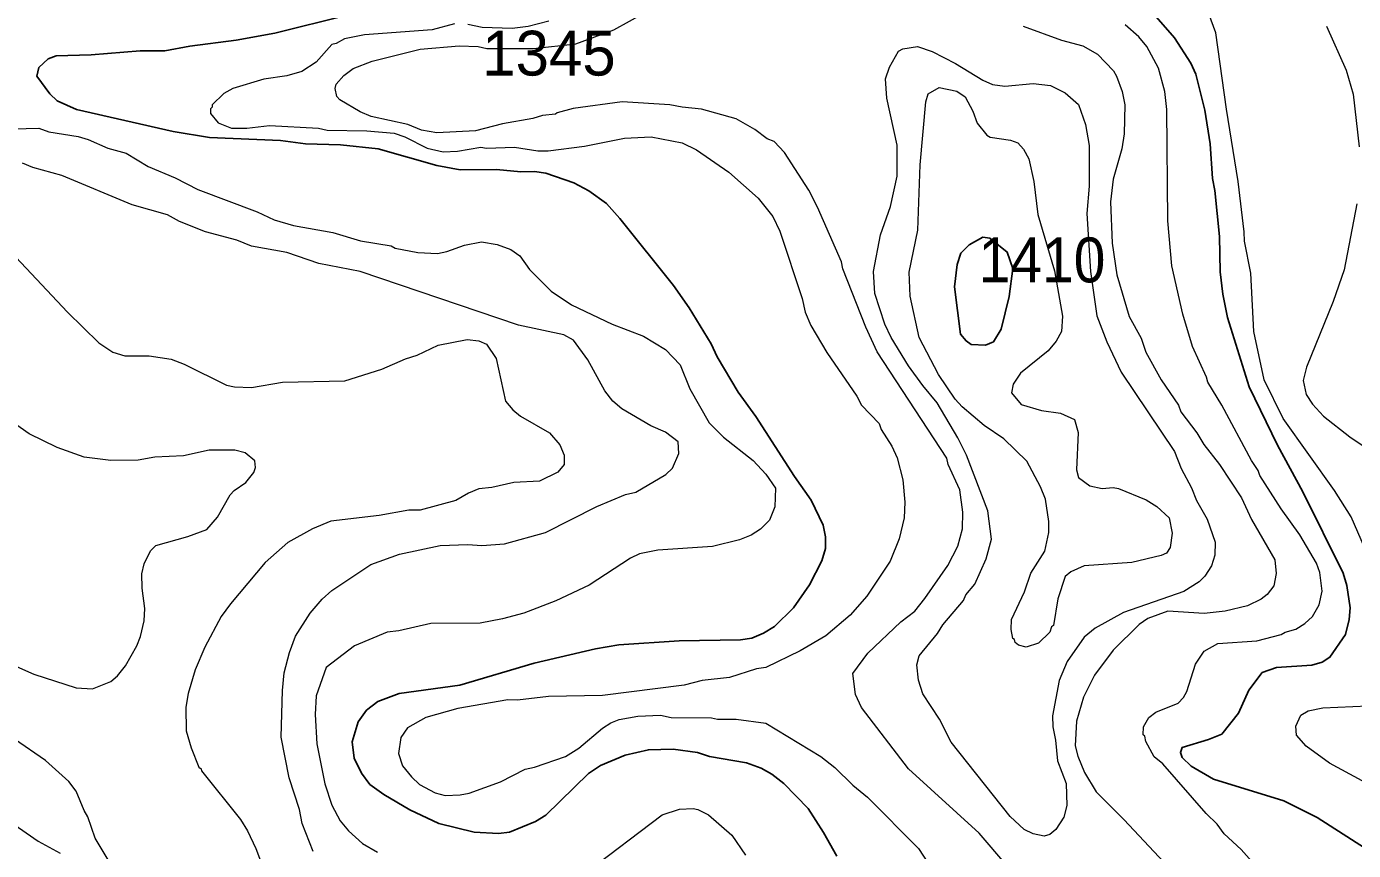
# Model space of a CAD drawing. Extents: x 598.3 to 623.2, y 6902.2 to 6930.1.
# Drawn here: x 600.767 to 603.134, y 6914.004 to 6915.474 of the extents above; entities that cross this region are included whole.
import ezdxf

# ---------------------------------------------------------------- set-up
doc = ezdxf.new("R2010")
doc.units = 0
doc.header["$LTSCALE"] = 0.032
doc.layers.add('1', color=7, linetype='Continuous', lineweight=25)
doc.layers.add('2', color=7, linetype='Continuous', lineweight=13)
doc.layers.add('21', color=7, linetype='Continuous')

msp = doc.modelspace()

# ---------------------------------------------------------------- linework, layer by layer
at = {"layer": '1'}
for points in [[(602.7571, 6915.5205), (602.8149, 6915.4545), (602.8438, 6915.4089), (602.8527, 6915.3895), (602.8692, 6915.3253), (602.8787, 6915.2648), (602.8827, 6915.203), (602.8869, 6915.1816), (602.8949, 6915.0997), (602.8965, 6915.0365), (602.9013, 6914.9965), (602.9095, 6914.955), (602.9478, 6914.8315), (602.9985, 6914.727), (603.044, 6914.6442), (603.1158, 6914.499), (603.1225, 6914.477), (603.128, 6914.4369), (603.1264, 6914.4162), (603.1199, 6914.3894), (603.0922, 6914.3488), (603.0781, 6914.3402)], [(602.1883, 6914.5842), (602.1668, 6914.629), (602.1368, 6914.6711), (602.0681, 6914.7782), (602.0364, 6914.8216), (601.9992, 6914.885), (601.9883, 6914.9083), (601.949, 6914.9722), (601.9213, 6915.0123), (601.8254, 6915.132), (601.8013, 6915.1585), (601.7702, 6915.1813), (601.7433, 6915.1956), (601.6933, 6915.2128), (601.6729, 6915.2159), (601.6484, 6915.2152), (601.6055, 6915.2193), (601.5406, 6915.2188), (601.499, 6915.2266), (601.3941, 6915.2564), (601.327, 6915.263), (601.2646, 6915.2653), (601.2196, 6915.271), (601.0929, 6915.2765), (601.0282, 6915.2872), (600.8559, 6915.3263), (600.8213, 6915.3419), (600.8085, 6915.3541), (600.7854, 6915.3858), (600.7887, 6915.4013), (600.8054, 6915.4166), (600.8194, 6915.4223), (600.8822, 6915.424), (600.9696, 6915.4312), (601.0134, 6915.4312), (601.0582, 6915.4395), (601.1406, 6915.45), (601.2095, 6915.4628), (601.3388, 6915.4944)], [(602.2125, 6913.9936), (602.1889, 6914.036), (602.1612, 6914.0788), (602.1181, 6914.1237), (602.0965, 6914.1403), (602.0776, 6914.1505), (602.0515, 6914.1606), (601.9853, 6914.1717), (601.964, 6914.179), (601.9206, 6914.1846), (601.8763, 6914.1838), (601.8345, 6914.1741), (601.7908, 6914.1555), (601.7696, 6914.1414), (601.6934, 6914.0672), (601.6749, 6914.0555), (601.6286, 6914.0365), (601.6085, 6914.0342), (601.5654, 6914.0366), (601.5025, 6914.0522), (601.4508, 6914.0762), (601.404, 6914.1039), (601.3793, 6914.1218), (601.3645, 6914.1417), (601.3512, 6914.1688), (601.348, 6914.1979), (601.3586, 6914.2332), (601.373, 6914.2541), (601.3933, 6914.2696), (601.4316, 6914.2843), (601.5401, 6914.2989), (601.6724, 6914.338), (601.7817, 6914.3637), (601.8234, 6914.3709), (601.9309, 6914.3781), (602.0404, 6914.3798), (602.0608, 6914.383), (602.0815, 6914.3916), (602.1011, 6914.4035), (602.135, 6914.437), (602.1639, 6914.4779), (602.1855, 6914.5207), (602.1922, 6914.5426), (602.1922, 6914.5638), (602.1883, 6914.5842)], [(603.0781, 6914.3402), (603.06, 6914.3345), (602.9969, 6914.3303), (602.9713, 6914.3215), (602.9477, 6914.2902), (602.9293, 6914.2488), (602.8991, 6914.2116), (602.8758, 6914.2017), (602.8286, 6914.1878), (602.8255, 6914.1788), (602.8288, 6914.1698), (602.8443, 6914.1543), (602.8843, 6914.1309), (603.0102, 6914.0923), (603.0696, 6914.0626), (603.1537, 6914.0084)]]:
    msp.add_lwpolyline(points, dxfattribs=at)
msp.add_lwpolyline([(602.5055, 6914.934), (602.5201, 6914.9924), (602.5262, 6915.0424), (602.5162, 6915.0718), (602.4856, 6915.0967), (602.473, 6915.0985), (602.4483, 6915.085), (602.4336, 6915.0701), (602.4271, 6915.0495), (602.4222, 6915.0096), (602.4332, 6914.9252), (602.443, 6914.9134), (602.4519, 6914.9069), (602.4779, 6914.9058), (602.4919, 6914.9119)], close=True, dxfattribs=at)
at = {"layer": '2'}
for points in [[(601.7136, 6915.3205), (601.7105, 6915.3178), (601.6871, 6915.3155), (601.6701, 6915.3104), (601.6162, 6915.301), (601.5676, 6915.2881), (601.4987, 6915.2846), (601.4716, 6915.2897), (601.4473, 6915.2994), (601.3818, 6915.3138), (601.3617, 6915.322), (601.3255, 6915.3436), (601.3201, 6915.3495), (601.3173, 6915.364), (601.319, 6915.3714), (601.3327, 6915.3869), (601.3494, 6915.3992), (601.3831, 6915.4127), (601.4689, 6915.4338), (601.5386, 6915.4402), (601.5725, 6915.4385), (601.5879, 6915.4354), (601.6715, 6915.4349), (601.7467, 6915.4435), (601.8145, 6915.4683), (601.8984, 6915.515)], [(603.1597, 6914.5309), (603.1303, 6914.5994), (603.1005, 6914.6461), (603.0089, 6914.7746), (602.9747, 6914.8439), (602.9563, 6914.9303), (602.9508, 6915.0344), (602.9395, 6915.0911), (602.9394, 6915.1078), (602.9282, 6915.1979), (602.9077, 6915.3269), (602.8885, 6915.4634), (602.8677, 6915.5195)], [(601.6988, 6915.4841), (601.6618, 6915.4742), (601.6329, 6915.471), (601.5798, 6915.4726), (601.5539, 6915.4783)], [(601.5301, 6915.479), (601.4902, 6915.4686), (601.3696, 6915.4598), (601.3342, 6915.4523), (601.3192, 6915.4441), (601.3112, 6915.4423), (601.2836, 6915.4107), (601.2578, 6915.3939), (601.2313, 6915.3865), (601.1904, 6915.3803), (601.1346, 6915.3639), (601.1185, 6915.3548), (601.098, 6915.3349), (601.0978, 6915.3304), (601.0947, 6915.3274), (601.0949, 6915.3194), (601.1084, 6915.3028), (601.1324, 6915.2933), (601.16, 6915.2929), (601.2004, 6915.2977), (601.2876, 6915.2928), (601.3029, 6915.2897), (601.3737, 6915.288), (601.4228, 6915.284), (601.4417, 6915.2775), (601.4815, 6915.2572), (601.5102, 6915.2508), (601.5357, 6915.2522), (601.5771, 6915.2588), (601.5872, 6915.2572)], [(602.5447, 6915.4749), (602.613, 6915.45), (602.6512, 6915.4397), (602.6776, 6915.4252), (602.7058, 6915.3952), (602.7116, 6915.3857), (602.7217, 6915.3582), (602.7265, 6915.3344), (602.725, 6915.2826), (602.7207, 6915.2559), (602.7055, 6915.202), (602.7007, 6915.1618), (602.7038, 6915.088), (602.712, 6915.0312), (602.7339, 6914.9566), (602.7555, 6914.9183), (602.764, 6914.8933), (602.7912, 6914.8439), (602.8218, 6914.7985), (602.8263, 6914.7866), (602.8546, 6914.7495), (602.8669, 6914.7282), (602.8949, 6914.693), (602.9345, 6914.6331), (602.9522, 6914.5946), (602.9937, 6914.5225), (602.9961, 6914.4982), (602.992, 6914.4764), (602.9801, 6914.461), (602.9694, 6914.4526), (602.9452, 6914.4405), (602.9052, 6914.4308), (602.868, 6914.4268), (602.8027, 6914.4307), (602.767, 6914.4178), (602.7517, 6914.4074), (602.7057, 6914.3613), (602.672, 6914.3169)], [(602.9619, 6914.3782), (603.0053, 6914.3895), (603.0122, 6914.3937), (603.0315, 6914.399), (603.0471, 6914.4088), (603.0609, 6914.4212), (603.073, 6914.4424), (603.0786, 6914.4665), (603.0739, 6914.5002), (603.068, 6914.5168), (603.0384, 6914.5673), (603.0052, 6914.6135), (602.9671, 6914.6734), (602.9642, 6914.6823), (602.9521, 6914.7), (602.8991, 6914.7988), (602.8741, 6914.8398), (602.8721, 6914.8487), (602.8472, 6914.9033), (602.8299, 6914.961), (602.81, 6915.0474), (602.8027, 6915.1276), (602.801, 6915.3266), (602.7978, 6915.3582), (602.7865, 6915.4003), (602.7654, 6915.4385), (602.7512, 6915.456), (602.7271, 6915.4776)], [(603.0861, 6915.4748), (603.1213, 6915.3963), (603.1338, 6915.3534), (603.1443, 6915.2595)], [(602.5156, 6913.9772), (602.4662, 6914.0345), (602.3401, 6914.1494), (602.2562, 6914.2591), (602.2457, 6914.2821), (602.241, 6914.3198), (602.2675, 6914.3563), (602.3268, 6914.4122), (602.3513, 6914.4311), (602.3697, 6914.4537), (602.4103, 6914.5123), (602.4282, 6914.5467), (602.4367, 6914.5779), (602.4375, 6914.6075), (602.4319, 6914.6477), (602.4111, 6914.6925), (602.4084, 6914.7043), (602.2844, 6914.8941), (602.2642, 6914.9378), (602.2234, 6915.0418), (602.2205, 6915.0543), (602.178, 6915.1523), (602.1622, 6915.1822), (602.119, 6915.2494), (602.1009, 6915.2692), (602.0883, 6915.2737), (602.066, 6915.2904), (602.0331, 6915.3097), (601.9708, 6915.3268), (601.9363, 6915.3302), (601.9144, 6915.3349), (601.8292, 6915.3399), (601.7423, 6915.3279), (601.7136, 6915.3205)], [(600.7217, 6915.2913), (600.7886, 6915.2928), (600.8064, 6915.2863), (600.8588, 6915.2781), (600.8768, 6915.273), (600.9117, 6915.2573), (600.9443, 6915.2482), (600.984, 6915.2243), (601.0318, 6915.2045), (601.0724, 6915.1833), (601.1781, 6915.1436), (601.2087, 6915.1297), (601.2428, 6915.1194), (601.313, 6915.1067), (601.3626, 6915.0919), (601.4174, 6915.0832), (601.4242, 6915.079), (601.4648, 6915.0711), (601.4999, 6915.0695), (601.5169, 6915.073), (601.5482, 6915.0841), (601.5782, 6915.0903), (601.6065, 6915.0856), (601.6308, 6915.0766), (601.6469, 6915.0651), (601.664, 6915.0406), (601.7029, 6915.0018), (601.739, 6914.9779), (601.8118, 6914.9431), (601.8672, 6914.922), (601.9069, 6914.8982), (601.933, 6914.8707), (601.95, 6914.8277), (601.9849, 6914.767), (602.0101, 6914.7415), (602.0632, 6914.6999), (602.0858, 6914.6757), (602.1031, 6914.6507), (602.1016, 6914.6169), (602.0922, 6914.5931), (602.076, 6914.5774), (602.0593, 6914.5666), (602.0386, 6914.5582), (601.9905, 6914.5466)], [(601.5872, 6915.2572), (601.6373, 6915.2588), (601.6787, 6915.2525), (601.6975, 6915.2524), (601.7623, 6915.261), (601.8335, 6915.2751), (601.8809, 6915.2774), (601.9363, 6915.267), (601.9621, 6915.2542), (602.0196, 6915.2145), (602.072, 6915.1679), (602.0982, 6915.1352), (602.1106, 6915.1089), (602.1503, 6914.9888), (602.1559, 6914.9648), (602.1663, 6914.9407), (602.1944, 6914.8926), (602.248, 6914.8146), (602.2567, 6914.7987), (602.2877, 6914.7659), (602.2916, 6914.755), (602.3103, 6914.7257), (602.3202, 6914.7049), (602.33, 6914.6653), (602.3339, 6914.6253), (602.3323, 6914.5975), (602.3234, 6914.5603), (602.3075, 6914.5203), (602.2657, 6914.458), (602.2364, 6914.4239), (602.1925, 6914.3872), (602.147, 6914.36), (602.0857, 6914.3304), (602.069, 6914.3279), (602.021, 6914.3126), (601.9724, 6914.307), (601.9403, 6914.2989), (601.7943, 6914.2802), (601.698, 6914.2785), (601.6424, 6914.2721), (601.6256, 6914.2729), (601.5364, 6914.2575), (601.4791, 6914.241), (601.4462, 6914.2229), (601.4346, 6914.2057), (601.4306, 6914.177), (601.4373, 6914.1551), (601.4534, 6914.1351), (601.4678, 6914.1217), (601.496, 6914.1065), (601.5137, 6914.1022), (601.5404, 6914.103), (601.5563, 6914.1062), (601.6125, 6914.1263), (601.6564, 6914.149), (601.6729, 6914.1523), (601.7282, 6914.1717), (601.7523, 6914.1863), (601.7942, 6914.2221), (601.8091, 6914.2319), (601.8243, 6914.2379), (601.8574, 6914.2438), (601.8976, 6914.2453), (601.9168, 6914.2414), (601.9888, 6914.2406), (601.9994, 6914.2381), (602.0326, 6914.238), (602.0857, 6914.2309), (602.1839, 6914.1714), (602.2089, 6914.1519), (602.2408, 6914.1202), (602.2671, 6914.0993), (602.3584, 6914.0072), (602.4235, 6913.9068)], [(601.7251, 6914.9241), (601.6443, 6914.9413), (601.362, 6915.037), (601.2882, 6915.0514), (601.2309, 6915.071), (601.1679, 6915.0825), (601.1419, 6915.0929), (601.0858, 6915.1081), (601.0396, 6915.1265), (601.0183, 6915.1383), (600.9552, 6915.1564), (600.83, 6915.2083), (600.7779, 6915.2231), (600.7598, 6915.2305)], [(603.1402, 6915.158), (603.1173, 6915.0402), (603.0978, 6914.9836), (603.0503, 6914.8662), (603.0447, 6914.8429), (603.0497, 6914.8175), (603.0608, 6914.8004), (603.0809, 6914.779), (603.1279, 6914.7419), (603.173, 6914.712)], [(600.7293, 6915.0826), (600.8397, 6914.9648), (600.896, 6914.9101), (600.9209, 6914.893), (600.9424, 6914.8865), (600.9856, 6914.8865), (601.0248, 6914.8809), (601.048, 6914.8718), (601.1233, 6914.8343), (601.1377, 6914.8313), (601.1681, 6914.8299), (601.2235, 6914.8395), (601.3348, 6914.8419), (601.4004, 6914.8629), (601.4427, 6914.8816), (601.4635, 6914.888), (601.5013, 6914.906), (601.5526, 6914.9156), (601.5736, 6914.9133), (601.5875, 6914.9074), (601.6046, 6914.8819), (601.6213, 6914.8057), (601.6344, 6914.7904), (601.6479, 6914.7792), (601.6999, 6914.749), (601.7182, 6914.7281), (601.726, 6914.7092), (601.726, 6914.6925), (601.7145, 6914.6791), (601.6819, 6914.6631)], [(601.2781, 6914.0022), (601.2585, 6914.0518), (601.2539, 6914.0768), (601.2352, 6914.1338), (601.2209, 6914.2064), (601.2234, 6914.2892), (601.2266, 6914.321), (601.2359, 6914.3575), (601.2465, 6914.3865), (601.2729, 6914.4277), (601.2941, 6914.4522), (601.3115, 6914.468), (601.381, 6914.514), (601.4319, 6914.5329), (601.5045, 6914.5482), (601.5543, 6914.5498), (601.5793, 6914.5482), (601.6194, 6914.5514), (601.6926, 6914.5711), (601.7841, 6914.6176), (601.8355, 6914.6392), (601.8537, 6914.6436), (601.9071, 6914.6751), (601.9191, 6914.6862), (601.9308, 6914.7124), (601.9293, 6914.733), (601.9068, 6914.7504), (601.8803, 6914.7616), (601.8289, 6914.792), (601.813, 6914.806), (601.7986, 6914.8241), (601.768, 6914.8795), (601.7424, 6914.9146), (601.7251, 6914.9241)], [(600.7066, 6914.3507), (600.7797, 6914.3186), (600.855, 6914.2939), (600.8847, 6914.2925), (600.9172, 6914.3053), (600.929, 6914.3155), (600.9432, 6914.3337), (600.9633, 6914.369), (600.97, 6914.3857), (600.9765, 6914.4135), (600.9781, 6914.4356), (600.9731, 6914.4722), (600.9722, 6914.4978), (600.9765, 6914.5152), (600.9877, 6914.5389), (600.9977, 6914.5481), (601.0544, 6914.5644), (601.0883, 6914.5767), (601.1072, 6914.5986), (601.1298, 6914.6385), (601.137, 6914.6462), (601.1578, 6914.6608), (601.1721, 6914.6784), (601.1755, 6914.6876), (601.1739, 6914.6993), (601.1568, 6914.7136), (601.1384, 6914.7182), (601.0928, 6914.7181), (601.0466, 6914.7085), (600.9957, 6914.7061), (600.9657, 6914.7004), (600.9172, 6914.6996), (600.8694, 6914.706), (600.8213, 6914.7228), (600.7717, 6914.7475), (600.7295, 6914.7772)], [(601.6819, 6914.6631), (601.6364, 6914.6606), (601.5968, 6914.6518), (601.5738, 6914.6493), (601.555, 6914.6415), (601.5327, 6914.6282), (601.4689, 6914.6113), (601.449, 6914.6112), (601.3958, 6914.6017), (601.3099, 6914.5918), (601.2769, 6914.5778), (601.2332, 6914.5536), (601.1926, 6914.5181), (601.1306, 6914.4442), (601.1142, 6914.4213), (601.0847, 6914.367), (601.0676, 6914.3261), (601.0554, 6914.2843), (601.051, 6914.2594), (601.0517, 6914.2173), (601.0606, 6914.1869), (601.0744, 6914.1525), (601.0783, 6914.1498), (601.0788, 6914.1463), (601.1484, 6914.059), (601.1611, 6914.0387), (601.1761, 6914.0072), (601.2032, 6913.9349)], [(601.9905, 6914.5466), (601.8931, 6914.5401), (601.8604, 6914.5335), (601.844, 6914.5253), (601.7703, 6914.4772), (601.7112, 6914.4493), (601.6537, 6914.4277), (601.6162, 6914.4171), (601.5763, 6914.4098), (601.488, 6914.4089), (601.4311, 6914.3959), (601.41, 6914.3936), (601.3518, 6914.3691), (601.3011, 6914.3303), (601.2832, 6914.28), (601.2816, 6914.2466), (601.2849, 6914.194), (601.2987, 6914.1229), (601.3115, 6914.0846), (601.3261, 6914.0569), (601.3414, 6914.0389), (601.3661, 6914.0161), (601.3927, 6914.0008)], [(603.1641, 6913.7074), (603.123, 6913.7508), (603.0476, 6913.8557), (603.0232, 6913.8862), (602.9722, 6913.9625), (602.9336, 6914.0059), (602.9036, 6914.0335), (602.8912, 6914.0508), (602.8714, 6914.07), (602.7941, 6914.1583), (602.7783, 6914.1712), (602.764, 6914.1986), (602.7621, 6914.2079), (602.759, 6914.21), (602.7593, 6914.2245), (602.7689, 6914.2415), (602.7816, 6914.251), (602.8212, 6914.2665), (602.8311, 6914.2772), (602.837, 6914.2877), (602.8526, 6914.3363), (602.8675, 6914.3596), (602.892, 6914.3732), (602.9619, 6914.3782)], [(602.672, 6914.3169), (602.6523, 6914.2775), (602.6403, 6914.2346), (602.6375, 6914.1909), (602.6423, 6914.172), (602.6543, 6914.1431), (602.6749, 6914.1085), (602.7253, 6914.0587), (602.8406, 6913.9353), (602.8515, 6913.9154), (602.8736, 6913.8614), (602.8918, 6913.8334), (602.9286, 6913.7965), (602.9572, 6913.7752), (603.0133, 6913.7515), (603.0299, 6913.7396), (603.0416, 6913.7246), (603.0604, 6913.6901), (603.1086, 6913.5309), (603.1457, 6913.4734)], [(603.1496, 6914.1282), (603.0913, 6914.16), (603.0495, 6914.1903), (603.0324, 6914.2095), (603.0316, 6914.2259), (603.0404, 6914.2451), (603.0534, 6914.2532), (603.0793, 6914.2583), (603.1595, 6914.2622)], [(600.9125, 6913.9869), (600.8891, 6914.026), (600.8764, 6914.064), (600.8693, 6914.0752), (600.8553, 6914.1097), (600.8424, 6914.1269), (600.8007, 6914.1646), (600.7452, 6914.2023)], [(600.6756, 6914.0979), (600.7875, 6914.0208)], [(601.766, 6913.9652), (601.9005, 6914.0676), (601.9319, 6914.0779), (601.9562, 6914.0786), (601.9646, 6914.0768), (601.9832, 6914.0675), (602.0249, 6914.0314), (602.0497, 6913.9955)], [(600.7875, 6914.0208), (600.8269, 6913.9992)]]:
    msp.add_lwpolyline(points, dxfattribs=at)
for points in [[(602.3301, 6915.4345), (602.3563, 6915.4385), (602.3824, 6915.43), (602.4241, 6915.4085), (602.4727, 6915.3785), (602.49, 6915.3709), (602.5122, 6915.3682), (602.5628, 6915.373), (602.5936, 6915.369), (602.6195, 6915.3562), (602.6438, 6915.335), (602.6563, 6915.2996), (602.6626, 6915.2619), (602.6627, 6915.1895), (602.6585, 6915.1409), (602.6649, 6915.037), (602.6763, 6914.9581), (602.6941, 6914.9117), (602.7195, 6914.8577), (602.8146, 6914.716), (602.8267, 6914.6855), (602.8454, 6914.6512), (602.8543, 6914.6286), (602.8733, 6914.5954), (602.8875, 6914.5544), (602.8868, 6914.5312), (602.8811, 6914.5117), (602.8692, 6914.4937), (602.859, 6914.4832), (602.8313, 6914.4661), (602.7236, 6914.4284), (602.6731, 6914.4007), (602.6538, 6914.3846), (602.6234, 6914.3412), (602.6091, 6914.3075), (602.5971, 6914.2439), (602.5977, 6914.2245), (602.6027, 6914.2006), (602.6059, 6914.1639), (602.6213, 6914.1237), (602.6229, 6914.0844), (602.6172, 6914.0632), (602.6034, 6914.0415), (602.5923, 6914.0326), (602.5825, 6914.0293), (602.5628, 6914.0337), (602.5469, 6914.0416), (602.5219, 6914.0646), (602.4166, 6914.1974), (602.3954, 6914.2381), (602.3657, 6914.2832), (602.3579, 6914.3076), (602.355, 6914.3355), (602.3595, 6914.3514), (602.3922, 6914.3911), (602.4015, 6914.4063), (602.4383, 6914.4503), (602.4428, 6914.4604), (602.4584, 6914.4791), (602.4788, 6914.5246), (602.4885, 6914.5597), (602.4821, 6914.6102), (602.4439, 6914.7095), (602.4285, 6914.7403), (602.3916, 6914.8029), (602.3658, 6914.8335), (602.34, 6914.869), (602.3096, 6914.9197), (602.298, 6914.9433), (602.2805, 6914.9977), (602.2781, 6915.0372), (602.2903, 6915.1029), (602.3082, 6915.1534), (602.3201, 6915.2073), (602.3202, 6915.2627), (602.3016, 6915.3465), (602.2992, 6915.3808), (602.3063, 6915.4019), (602.3227, 6915.4304)], [(602.5222, 6915.2718), (602.5354, 6915.2669), (602.5452, 6915.2556), (602.555, 6915.2384), (602.5639, 6915.1979), (602.5709, 6915.1392), (602.6009, 6915.0385), (602.615, 6914.9572), (602.6131, 6914.9302), (602.6037, 6914.9126), (602.5897, 6914.8954), (602.5404, 6914.8558), (602.5269, 6914.836), (602.5242, 6914.8204), (602.5414, 6914.7999), (602.5774, 6914.7894), (602.6116, 6914.7845), (602.6364, 6914.7732), (602.6431, 6914.7497), (602.64, 6914.6831), (602.6436, 6914.6693), (602.6637, 6914.6549), (602.6856, 6914.6502), (602.7055, 6914.6518), (602.7152, 6914.6501), (602.7641, 6914.6297), (602.7832, 6914.6177), (602.8056, 6914.5976), (602.8107, 6914.5703), (602.8069, 6914.5444), (602.8005, 6914.5347), (602.7913, 6914.5303), (602.7388, 6914.5176), (602.6537, 6914.5117), (602.6301, 6914.5012), (602.6195, 6914.4926), (602.6067, 6914.453), (602.5987, 6914.4054), (602.5954, 6914.403), (602.5926, 6914.3937), (602.5725, 6914.3741), (602.5501, 6914.3669), (602.5368, 6914.3703), (602.5308, 6914.3749), (602.5296, 6914.3806), (602.5267, 6914.3825), (602.5234, 6914.3982), (602.5242, 6914.4159), (602.547, 6914.4653), (602.5586, 6914.4988), (602.5835, 6914.5382), (602.5905, 6914.5716), (602.5905, 6914.5913), (602.5845, 6914.6309), (602.5757, 6914.6531), (602.5512, 6914.6984), (602.5104, 6914.7384), (602.4751, 6914.7622), (602.4361, 6914.7957), (602.4234, 6914.8096), (602.394, 6914.8533), (602.3591, 6914.9192), (602.343, 6914.9931), (602.3417, 6915.0362), (602.3567, 6915.111), (602.3608, 6915.2277), (602.3711, 6915.34), (602.3754, 6915.3544), (602.3949, 6915.3656), (602.4263, 6915.3591), (602.4414, 6915.3488), (602.455, 6915.3234), (602.4627, 6915.3019), (602.4799, 6915.2804), (602.4857, 6915.2771)]]:
    msp.add_lwpolyline(points, close=True, dxfattribs=at)

# ---------------------------------------------------------------- texts
at = {"layer": '21'}
msp.add_text('1345', height=0.08, dxfattribs=at).set_placement((601.5798, 6915.3869))
at = {"layer": '21', "width": 0.95}
msp.add_text('1410', height=0.08, dxfattribs=at).set_placement((602.4655, 6915.0179))

doc.saveas('drawing.dxf')
